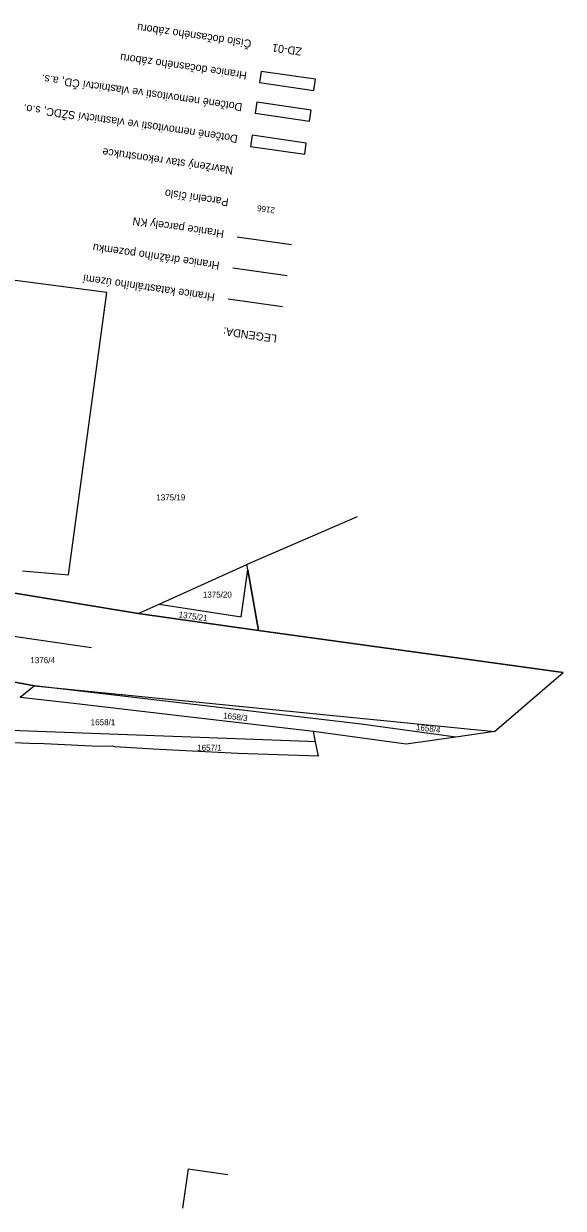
# Model space of a CAD drawing. Extents: x -757895 to -757311, y -1060303 to -1059942.
# Drawn here: x -757446.3 to -757311.4, y -1060302.6 to -1060006.6 of the extents above; entities that cross this region are included whole.
import ezdxf

# ---------------------------------------------------------------- set-up
doc = ezdxf.new("R2010")
doc.units = 0
for name, color, linetype in [('Dočasné zábory', 7, 'Continuous'), ('Dočasné zábory - čísla', 7, 'Continuous'), ('Legenda 1', 7, 'Continuous'), ('Legenda 2', 7, 'Continuous'), ('Level 53', 7, 'Continuous'), ('Pozemky SŽDC', 7, 'Continuous'), ('Pozemky ČD', 7, 'Continuous'), ('Vrstva 1', 7, 'Continuous'), ('Vrstva 53', 7, 'Continuous'), ('Vrstva 55', 7, 'Continuous'), ('Vrstva 57', 7, 'Continuous')]:
    doc.layers.add(name, color=color, linetype=linetype)

msp = doc.modelspace()

# ---------------------------------------------------------------- linework, layer by layer
at = {"layer": 'Dočasné zábory'}
msp.add_lwpolyline([(-757373.37, -1060020.45), (-757386.93, -1060018.5), (-757387.33, -1060021.28), (-757373.77, -1060023.23)], close=True, dxfattribs=at)
at = {"layer": 'Legenda 1'}
for q in [(-757406.6, -1060302.59), (-757395.28, -1060294.12)]:
    msp.add_line((-757405.18, -1060292.69), q, dxfattribs=at)
at = {"layer": 'Level 53'}
msp.add_line((-757380.47, -1060069.6), (-757394.03, -1060067.64), dxfattribs=at)
at = {"layer": 'Pozemky SŽDC'}
msp.add_lwpolyline([(-757375.65, -1060036.4), (-757389.21, -1060034.44), (-757389.61, -1060037.23), (-757376.05, -1060039.18)], close=True, dxfattribs=at)
msp.add_lwpolyline([(-757470.38, -1060167.04), (-757443.58, -1060171.99), (-757328.56, -1060183.46), (-757311.39, -1060168.71), (-757387.56, -1060158.16), (-757417.66, -1060153.97), (-757419.22, -1060153.71), (-757450.04, -1060148.6)], dxfattribs=at)
at = {"layer": 'Pozemky ČD'}
msp.add_lwpolyline([(-757374.47, -1060028.14), (-757388.03, -1060026.18), (-757388.44, -1060028.96), (-757374.88, -1060030.92)], close=True, dxfattribs=at)
at = {"layer": 'Vrstva 1'}
msp.add_line((-757429.32, -1060162.53), (-757720.62, -1060120.47), dxfattribs=at)
at = {"layer": 'Vrstva 53'}
for points in [[(-757687.19, -1060114.38), (-757639.93, -1060124.17), (-757624.54, -1060126.42), (-757624.32, -1060124.22), (-757612.89, -1060124.84), (-757606.63, -1060125.23), (-757568.62, -1060130.44), (-757535.86, -1060133.35), (-757534.03, -1060136.19), (-757533.01, -1060136.32), (-757528.28, -1060137.03), (-757525.99, -1060137.35), (-757523.49, -1060137.59), (-757520.85, -1060137.84), (-757515.4, -1060138.37), (-757496.99, -1060140.91), (-757493.93, -1060141.33), (-757450.04, -1060148.6), (-757417.66, -1060153.97), (-757412.43, -1060151.61), (-757391.89, -1060154.81), (-757390.25, -1060143), (-757387.56, -1060158.16)], [(-757328.56, -1060183.46), (-757338.29, -1060184.85), (-757361.91, -1060181.63), (-757443.58, -1060171.99), (-757470.38, -1060167.04), (-757513.1, -1060164.5), (-757526.21, -1060162.71), (-757533.6, -1060161.43), (-757535.01, -1060161.18), (-757542.9, -1060160.49), (-757543.88, -1060160.4), (-757632.1, -1060146.3), (-757634.26, -1060145.96), (-757635.44, -1060145.86), (-757686.64, -1060138.39), (-757693.18, -1060137.43), (-757732.62, -1060131.67), (-757793.56, -1060122.78), (-757866, -1060118.97)]]:
    msp.add_lwpolyline(points, dxfattribs=at)
at = {"layer": 'Vrstva 55'}
for p, q in [((-757379.33, -1060061.86), (-757392.89, -1060059.9)), ((-757425.51, -1060073.71), (-757474.75, -1060067.35)), ((-757381.61, -1060077.34), (-757395.17, -1060075.38)), ((-757412.43, -1060151.61), (-757390.54, -1060141.71)), ((-757390.25, -1060143), (-757390.54, -1060141.71)), ((-757387.56, -1060158.16), (-757390.25, -1060143)), ((-757450.04, -1060148.6), (-757417.66, -1060153.97)), ((-757417.66, -1060153.97), (-757412.43, -1060151.61)), ((-757417.66, -1060153.97), (-757387.56, -1060158.16)), ((-757387.56, -1060158.16), (-757311.39, -1060168.71)), ((-757443.58, -1060171.99), (-757447.18, -1060174.91)), ((-757443.58, -1060171.99), (-757328.56, -1060183.46)), ((-757373.35, -1060185.99), (-757373.86, -1060183.46)), ((-757350.67, -1060186.62), (-757373.86, -1060183.46)), ((-757328.56, -1060183.46), (-757338.29, -1060184.85)), ((-757457.81, -1060185.8), (-757442.84, -1060186.4)), ((-757427.56, -1060187.16), (-757442.84, -1060186.4)), ((-757423.99, -1060187.1), (-757427.56, -1060187.16)), ((-757372.63, -1060189.61), (-757373.35, -1060185.99)), ((-757338.29, -1060184.85), (-757350.67, -1060186.62)), ((-757372.63, -1060189.61), (-757392.78, -1060188.96))]:
    msp.add_line(p, q, dxfattribs=at)
for points in [[(-757446.57, -1060143.26), (-757435.09, -1060144.26), (-757425.51, -1060073.71)], [(-757390.54, -1060141.71), (-757390.04, -1060141.48), (-757362.82, -1060129.73)], [(-757412.43, -1060151.61), (-757391.89, -1060154.81), (-757390.25, -1060143)], [(-757513.1, -1060164.5), (-757470.38, -1060167.04), (-757443.58, -1060171.99)], [(-757338.29, -1060184.85), (-757361.91, -1060181.63), (-757443.58, -1060171.99)], [(-757373.86, -1060183.46), (-757405.36, -1060179.78), (-757434.52, -1060176.38), (-757447.18, -1060174.91)], [(-757373.35, -1060185.99), (-757375.27, -1060185.92), (-757449.6, -1060183.18)], [(-757413.91, -1060187.83), (-757423.52, -1060187.25), (-757423.99, -1060187.1)], [(-757392.78, -1060188.96), (-757394.39, -1060188.87), (-757413.91, -1060187.83)]]:
    msp.add_lwpolyline(points, dxfattribs=at)

# ---------------------------------------------------------------- texts
at = {"layer": 'Dočasné zábory - čísla'}
msp.add_text('ZD-01', height=2, rotation=172.2261, dxfattribs=at).set_placement((-757376.67, -1060012.59))
at = {"layer": 'Legenda 2'}
for s, p in [('Číslo dočasného záboru', (-757389.25, -1060010.66)), ('Hranice dočasného záboru', (-757390.4, -1060018.58)), ('Dotčené nemovitosti ve vlastnictví ČD, a.s.', (-757391.54, -1060026.5)), ('Dotčené nemovitosti ve vlastnictví SŽDC, s.o.', (-757392.68, -1060034.41)), ('Navržený stav rekonstrukce', (-757393.83, -1060042.33)), ('Parcelní číslo', (-757394.97, -1060050.25)), ('Hranice parcely KN', (-757396.11, -1060058.17)), ('Hranice drážního pozemku', (-757397.25, -1060066.09)), ('Hranice katastrálního území', (-757398.4, -1060074)), ('LEGENDA:', (-757382.89, -1060084.35))]:
    msp.add_text(s, height=2, rotation=171.7882, dxfattribs=at).set_placement(p)
at = {"layer": 'Vrstva 57'}
for s, rotation, p in [('2166', 171.7882, (-757383.41, -1060052.53)), ('1375/21', 352, (-757407.63, -1060154.9)), ('1658/3', 353, (-757396.51, -1060180.14)), ('1658/4', 353, (-757348.29, -1060183.06))]:
    msp.add_text(s, height=1.5, rotation=rotation, dxfattribs=at).set_placement(p)
for s, p in [('1375/19', (-757413.15, -1060125.69)), ('1375/20', (-757401.51, -1060149.97)), ('1376/4', (-757444.63, -1060166.36)), ('1658/1', (-757429.54, -1060181.87)), ('1657/1', (-757402.93, -1060188.24))]:
    msp.add_text(s, height=1.5, dxfattribs=at).set_placement(p)

doc.saveas('drawing.dxf')
